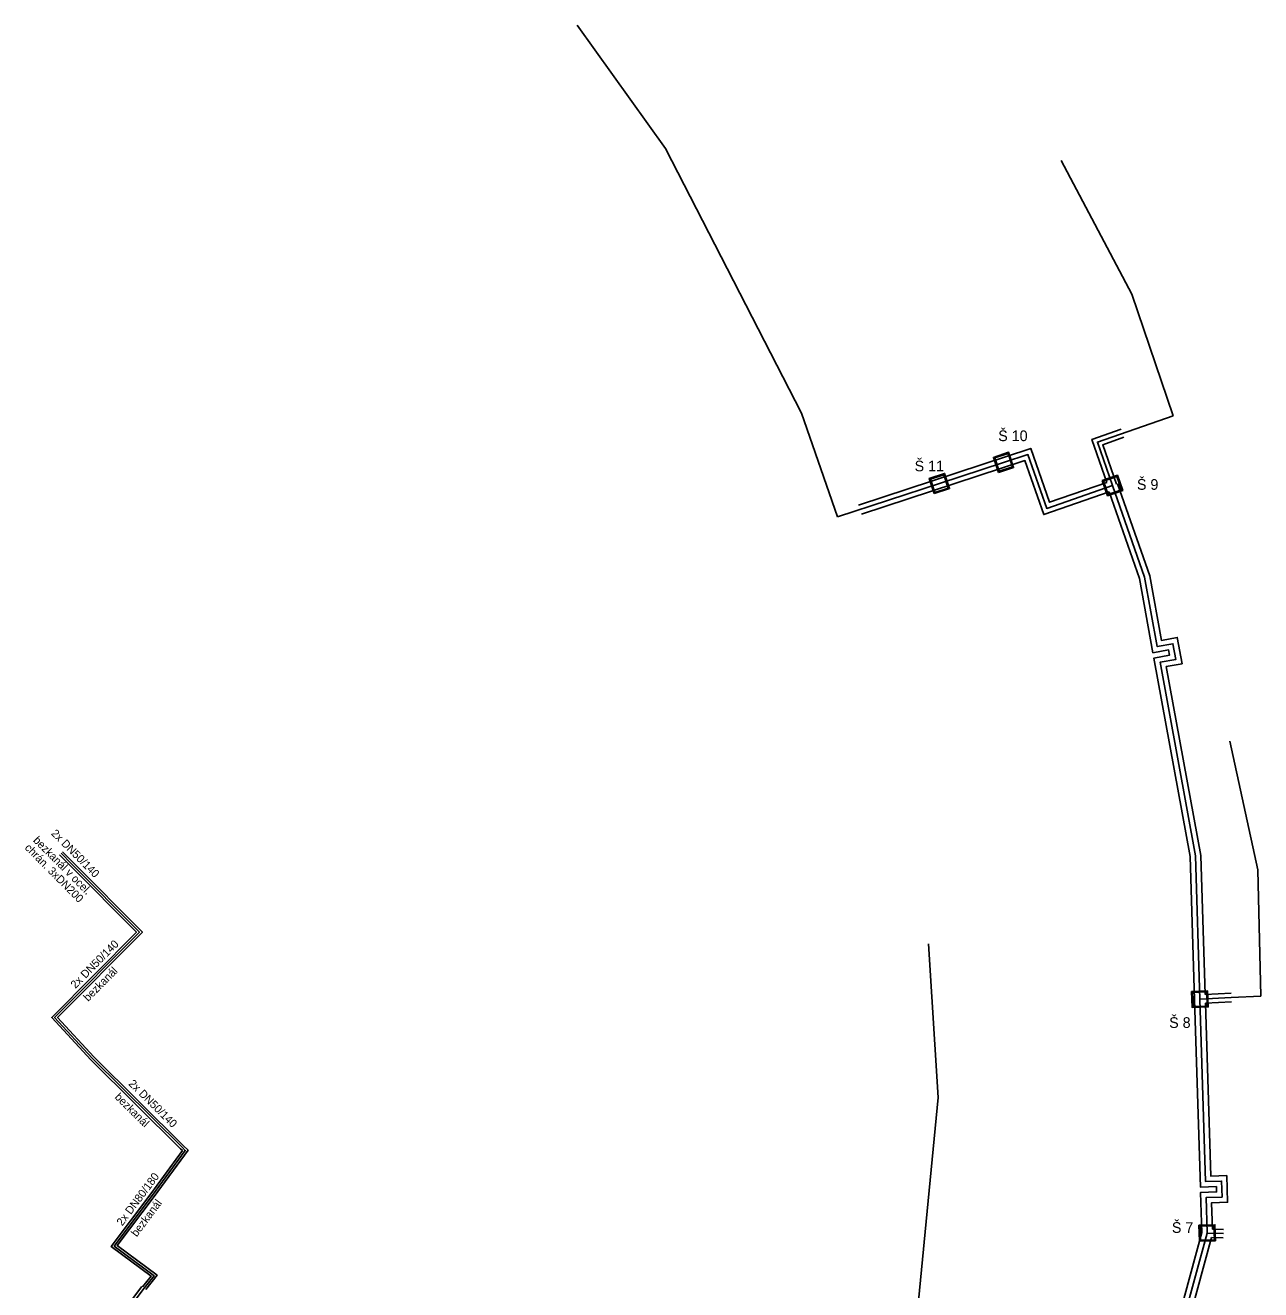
# Model space of a CAD drawing. Extents: x -606118 to -604472, y -1157869 to -1156854.
# Drawn here: x -605775.2 to -605543.6, y -1157459.8 to -1157222.8 of the extents above; entities that cross this region are included whole.
import ezdxf

# ---------------------------------------------------------------- set-up
doc = ezdxf.new("R2010")
doc.units = 0
for name, color, linetype in [('Osa trasy teplovodu', 7, 'Continuous'), ('označení šachty', 7, 'Continuous'), ('Teplovod - trasa - okraj', 7, 'Continuous'), ('Teplovod - trasa popis', 7, 'Continuous'), ('Teplovod - trasa popis 2', 7, 'Continuous'), ('Teplovod - trasa popis 3', 7, 'Continuous'), ('Šachta trasy teplovodu', 7, 'Continuous')]:
    doc.layers.add(name, color=color, linetype=linetype)

msp = doc.modelspace()

# ---------------------------------------------------------------- linework, layer by layer
at = {"layer": 'Osa trasy teplovodu'}
for p, q in [((-605766.56, -1157379.94), (-605768.5, -1157377.99)), ((-605555.03, -1157405.34), (-605549.13, -1157405.04)), ((-605571.57, -1157514.64), (-605553.65, -1157449.19)), ((-605553.65, -1157449.19), (-605550.62, -1157449.28))]:
    msp.add_line(p, q, dxfattribs=at)
for points in [[(-605622.92, -1157314.97), (-605629.69, -1157295.52), (-605655.22, -1157245.91), (-605671.77, -1157222.82)], [(-605581.05, -1157248.13), (-605567.79, -1157273.19), (-605560.01, -1157295.98)], [(-605571.4, -1157309.07), (-605574.24, -1157300.93), (-605560.01, -1157295.98)], [(-605571.4, -1157309.07), (-605583.74, -1157313.37), (-605587.27, -1157303.26), (-605591.83, -1157304.75), (-605603.84, -1157308.7), (-605622.92, -1157314.97)], [(-605555.03, -1157405.34), (-605555.87, -1157378.48), (-605562.48, -1157342.2), (-605559.53, -1157341.67), (-605560.07, -1157338.71), (-605563.02, -1157339.25), (-605565.39, -1157326.26), (-605571.4, -1157309.07)], [(-605549.13, -1157405.04), (-605543.62, -1157404.76), (-605544.17, -1157381.07), (-605549.42, -1157356.99)], [(-605745.82, -1157433.07), (-605762.65, -1157416.41), (-605769.69, -1157408.75), (-605753.79, -1157392.78), (-605766.56, -1157379.94)], [(-605615.19, -1157502.13), (-605609.46, -1157479.27), (-605604.1, -1157423.78), (-605605.91, -1157394.95)], [(-605553.65, -1157449.19), (-605553.65, -1157449.15), (-605553.65, -1157449.15), (-605553.86, -1157442.52), (-605550.86, -1157442.42), (-605550.95, -1157439.42), (-605553.95, -1157439.52), (-605555.03, -1157405.34)], [(-605752.94, -1157459.51), (-605751.05, -1157457.16), (-605758.51, -1157451.62), (-605751.36, -1157442.07), (-605745.22, -1157433.67), (-605745.82, -1157433.07)], [(-605771.99, -1157489.52), (-605769.28, -1157485.7), (-605771, -1157484.18), (-605762.81, -1157472.63), (-605752.94, -1157459.51)]]:
    msp.add_lwpolyline(points, dxfattribs=at)
at = {"layer": 'Teplovod - trasa - okraj'}
for p, q in [((-605766.84, -1157380.22), (-605768.78, -1157378.27)), ((-605768.21, -1157377.71), (-605766.27, -1157379.66)), ((-605554.05, -1157404.49), (-605549.17, -1157404.24)), ((-605554, -1157406.09), (-605549.09, -1157405.84)), ((-605572.54, -1157514.38), (-605554.65, -1157449.07)), ((-605552.67, -1157448.42), (-605550.59, -1157448.48)), ((-605570.39, -1157514.12), (-605552.84, -1157450.02)), ((-605552.84, -1157450.02), (-605550.64, -1157450.08))]:
    msp.add_line(p, q, dxfattribs=at)
for points in [[(-605572.45, -1157308.48), (-605575.26, -1157300.44), (-605569.78, -1157298.53)], [(-605570.64, -1157308.8), (-605573.22, -1157301.43), (-605569.25, -1157300.04)], [(-605572.45, -1157308.48), (-605583.19, -1157312.22), (-605586.72, -1157302.12), (-605619.04, -1157312.75)], [(-605572.05, -1157310.25), (-605584.29, -1157314.52), (-605587.83, -1157304.39), (-605618.48, -1157314.46)], [(-605554.05, -1157404.49), (-605554.87, -1157378.38), (-605561.32, -1157343.01), (-605558.37, -1157342.47), (-605559.27, -1157337.55), (-605562.22, -1157338.09), (-605564.42, -1157326), (-605570.45, -1157308.74)], [(-605556.03, -1157405.38), (-605556.86, -1157378.59), (-605563.65, -1157341.4), (-605560.7, -1157340.86), (-605560.88, -1157339.88), (-605563.83, -1157340.41), (-605566.36, -1157326.51), (-605572.05, -1157310.25)], [(-605746.11, -1157433.36), (-605762.94, -1157416.69), (-605770.24, -1157408.74), (-605754.36, -1157392.78), (-605766.84, -1157380.22)], [(-605766.27, -1157379.66), (-605753.23, -1157392.78), (-605769.14, -1157408.76), (-605762.37, -1157416.13), (-605745.54, -1157432.79)], [(-605554.65, -1157449.07), (-605554.89, -1157441.55), (-605551.89, -1157441.45), (-605551.92, -1157440.45), (-605554.92, -1157440.55), (-605556.03, -1157405.38)], [(-605552.67, -1157448.42), (-605552.83, -1157443.48), (-605549.83, -1157443.39), (-605549.99, -1157438.39), (-605552.98, -1157438.49), (-605554, -1157406.09)], [(-605745.54, -1157432.79), (-605744.69, -1157433.62), (-605751.04, -1157442.31), (-605757.95, -1157451.53), (-605750.48, -1157457.08), (-605752.62, -1157459.76)], [(-605753.25, -1157459.26), (-605751.63, -1157457.23), (-605759.07, -1157451.7), (-605751.68, -1157441.84), (-605745.74, -1157433.71), (-605746.11, -1157433.36)], [(-605772.39, -1157489.23), (-605769.94, -1157485.77), (-605771.67, -1157484.25), (-605763.21, -1157472.33), (-605753.33, -1157459.21)]]:
    msp.add_lwpolyline(points, dxfattribs=at)
at = {"layer": 'Šachta trasy teplovodu'}
for points in [[(-605592.79, -1157306.65), (-605593.73, -1157303.79), (-605590.87, -1157302.85), (-605589.93, -1157305.71), (-605592.79, -1157306.65)], [(-605590.17, -1157305.59), (-605590.99, -1157303.09), (-605593.49, -1157303.91), (-605592.67, -1157306.41), (-605590.17, -1157305.59)], [(-605604.8, -1157310.59), (-605605.74, -1157307.74), (-605602.88, -1157306.8), (-605601.95, -1157309.66), (-605604.8, -1157310.59)], [(-605602.18, -1157309.54), (-605603, -1157307.04), (-605605.5, -1157307.86), (-605604.68, -1157310.36), (-605602.18, -1157309.54)], [(-605573.31, -1157308.15), (-605570.47, -1157307.15), (-605569.48, -1157309.99), (-605572.32, -1157310.98), (-605573.31, -1157308.15)], [(-605572.2, -1157310.74), (-605569.72, -1157309.87), (-605570.59, -1157307.39), (-605573.07, -1157308.26), (-605572.2, -1157310.74)], [(-605556.57, -1157403.89), (-605553.57, -1157403.8), (-605553.47, -1157406.8), (-605556.48, -1157406.89), (-605556.57, -1157403.89)], [(-605556.29, -1157406.7), (-605553.67, -1157406.62), (-605553.75, -1157403.99), (-605556.38, -1157404.07), (-605556.29, -1157406.7)], [(-605555.2, -1157447.69), (-605552.19, -1157447.6), (-605552.1, -1157450.6), (-605555.1, -1157450.69), (-605555.2, -1157447.69)], [(-605554.92, -1157450.5), (-605552.29, -1157450.42), (-605552.38, -1157447.79), (-605555, -1157447.87), (-605554.92, -1157450.5)]]:
    msp.add_lwpolyline(points, dxfattribs=at)

# ---------------------------------------------------------------- texts
at = {"layer": 'označení šachty'}
for s, p in [('Š 10', (-605592.82, -1157300.75)), ('Š 11', (-605608.49, -1157306.41)), ('Š 9', (-605566.82, -1157309.87)), ('Š 8', (-605560.78, -1157410.72)), ('Š 7', (-605560.27, -1157449.13))]:
    msp.add_text(s, height=2, dxfattribs=at).set_placement(p)
at = {"layer": 'Teplovod - trasa popis'}
for s, rotation, p in [('2x DN50/140', 314.8067, (-605770.46, -1157374.39)), ('2x DN50/140', 45.1394, (-605765.81, -1157403.45)), ('2x DN50/140', 315.2897, (-605755.95, -1157421.3)), ('2x DN80/180', 53.1386, (-605757.02, -1157447.95))]:
    msp.add_text(s, height=1.5, rotation=rotation, dxfattribs=at).set_placement(p)
at = {"layer": 'Teplovod - trasa popis 2'}
for s, rotation, p in [('bezkanál v ocel.', 314.8067, (-605773.82, -1157375.69)), ('bezkanál', 45.1394, (-605763.42, -1157405.87)), ('bezkanál', 315.2897, (-605758.55, -1157423.8)), ('bezkanál', 53.1386, (-605754.31, -1157449.99))]:
    msp.add_text(s, height=1.5, rotation=rotation, dxfattribs=at).set_placement(p)
at = {"layer": 'Teplovod - trasa popis 3'}
msp.add_text('chrán. 3xDN200', height=1.5, rotation=314.8067, dxfattribs=at).set_placement((-605775.41, -1157377.08))

doc.saveas('drawing.dxf')
